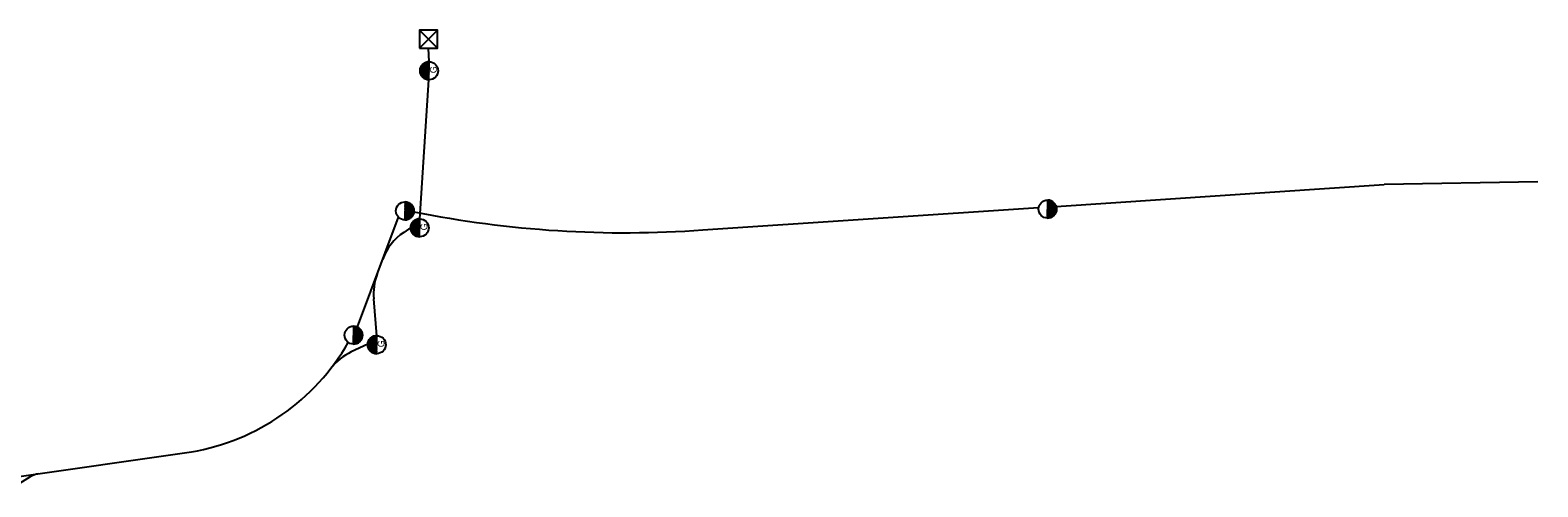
# Model space of a CAD drawing. Extents: x 584850 to 602551, y 145475 to 158627.
# Drawn here: x 586122 to 586791, y 156308 to 156511 of the extents above; entities that cross this region are included whole.
import ezdxf

# ---------------------------------------------------------------- set-up
doc = ezdxf.new("R2010")
doc.units = 0
doc.layers.add('Default', color=7, linetype='Continuous')

msp = doc.modelspace()

# ---------------------------------------------------------------- linework, layer by layer
at = {"layer": 'Default'}
for p, q in [((586294.93, 156502.64), (586302.93, 156510.64)), ((586294.93, 156510.64), (586302.93, 156502.64)), ((586299.27, 156496.61), (586298.93, 156502.64)), ((586299.19, 156496.6), (586295.2, 156492.76)), ((586299.26, 156496.34), (586295.21, 156492.44)), ((586299.26, 156496), (586295.23, 156492.12)), ((586298.82, 156496.58), (586295.24, 156493.14)), ((586299.25, 156495.66), (586295.28, 156491.84)), ((586298.41, 156496.52), (586295.3, 156493.52)), ((586299.24, 156495.32), (586295.34, 156491.56)), ((586299.24, 156494.98), (586295.42, 156491.31)), ((586297.95, 156496.41), (586295.46, 156494.01)), ((586295.47, 156494.05), (586299.15, 156490.23)), ((586299.23, 156494.65), (586295.51, 156491.07)), ((586295.57, 156494.29), (586299.15, 156490.57)), ((586299.22, 156494.31), (586295.61, 156490.83)), ((586295.69, 156494.51), (586299.16, 156490.91)), ((586299.22, 156493.97), (586295.74, 156490.62)), ((586297.33, 156496.15), (586295.75, 156494.62)), ((586295.81, 156494.74), (586299.17, 156491.25)), ((586295.95, 156494.93), (586299.17, 156491.59)), ((586296.1, 156495.13), (586299.18, 156491.93)), ((586296.25, 156495.32), (586299.19, 156492.27)), ((586296.43, 156495.48), (586299.19, 156492.61)), ((586296.6, 156495.64), (586299.2, 156492.95)), ((586296.79, 156495.8), (586299.2, 156493.29)), ((586296.99, 156495.93), (586299.21, 156493.63)), ((586297.2, 156496.07), (586299.22, 156493.97)), ((586297.42, 156496.18), (586299.22, 156494.31)), ((586297.65, 156496.28), (586299.23, 156494.65)), ((586297.89, 156496.39), (586299.24, 156494.98)), ((586298.15, 156496.46), (586299.24, 156495.32)), ((586298.42, 156496.52), (586299.25, 156495.66)), ((586298.71, 156496.57), (586299.26, 156496)), ((586299.02, 156496.59), (586299.26, 156496.34)), ((586299.12, 156488.61), (586299.27, 156496.61)), ((586299.22, 156496.61), (586299.27, 156496.56)), ((586295.1, 156426.81), (586299.12, 156488.61)), ((586295.21, 156492.94), (586299.12, 156488.88)), ((586295.21, 156492.6), (586299.04, 156488.61)), ((586295.21, 156492.24), (586298.67, 156488.65)), ((586295.26, 156493.24), (586299.13, 156489.22)), ((586295.28, 156491.82), (586298.26, 156488.73)), ((586295.3, 156493.53), (586299.13, 156489.56)), ((586295.39, 156493.79), (586299.14, 156489.89)), ((586295.41, 156491.35), (586297.79, 156488.88)), ((586295.68, 156490.72), (586297.17, 156489.18)), ((586299.21, 156493.63), (586295.87, 156490.4)), ((586299.2, 156493.29), (586296, 156490.21)), ((586299.2, 156492.95), (586296.16, 156490.02)), ((586299.19, 156492.61), (586296.32, 156489.84)), ((586299.19, 156492.27), (586296.49, 156489.67)), ((586299.18, 156491.93), (586296.68, 156489.52)), ((586299.17, 156491.59), (586296.86, 156489.36)), ((586299.17, 156491.25), (586297.07, 156489.23)), ((586299.16, 156490.91), (586297.29, 156489.11)), ((586299.15, 156490.57), (586297.51, 156488.99)), ((586299.15, 156490.23), (586297.75, 156488.89)), ((586299.14, 156489.89), (586298, 156488.8)), ((586299.13, 156489.56), (586298.28, 156488.73)), ((586299.13, 156489.22), (586298.56, 156488.67)), ((586299.12, 156488.88), (586298.86, 156488.63)), ((586299.12, 156488.61), (586299.12, 156488.61)), ((586299.12, 156488.61), (586299.12, 156488.61)), ((586303.1, 156493.59), (586303, 156493.55)), ((586577.42, 156432.35), (586723.02, 156442.06)), ((586791.19, 156443.23), (586723.02, 156442.06)), ((586288.53, 156434.33), (586288.38, 156426.33)), ((586288.48, 156431.68), (586290.58, 156433.7)), ((586288.49, 156432.36), (586290.14, 156433.95)), ((586288.49, 156432.02), (586290.36, 156433.83)), ((586288.5, 156432.7), (586289.89, 156434.04)), ((586288.51, 156433.38), (586289.37, 156434.21)), ((586288.51, 156433.04), (586289.65, 156434.14)), ((586288.52, 156433.72), (586289.08, 156434.26)), ((586292.39, 156429.7), (586288.52, 156433.72)), ((586288.53, 156434.33), (586288.53, 156434.32)), ((586288.53, 156434.33), (586288.53, 156434.32)), ((586288.53, 156434.06), (586288.79, 156434.31)), ((586292.44, 156430), (586288.53, 156434.06)), ((586292.44, 156430.34), (586288.61, 156434.32)), ((586292.43, 156430.69), (586288.97, 156434.29)), ((586292.36, 156431.11), (586289.38, 156434.21)), ((586292.24, 156431.59), (586289.86, 156434.06)), ((586291.97, 156432.21), (586290.48, 156433.76)), ((586573.68, 156435.14), (586573.53, 156427.14)), ((586573.6, 156430.8), (586576.64, 156433.73)), ((586573.61, 156431.48), (586576.31, 156434.07)), ((586573.61, 156431.14), (586576.48, 156433.91)), ((586573.62, 156431.82), (586576.12, 156434.23)), ((586573.63, 156432.5), (586575.73, 156434.52)), ((586573.63, 156432.16), (586575.94, 156434.39)), ((586573.64, 156433.17), (586575.29, 156434.76)), ((586573.64, 156432.84), (586575.51, 156434.64)), ((586573.65, 156433.51), (586575.04, 156434.86)), ((586573.66, 156434.19), (586574.52, 156435.02)), ((586573.66, 156433.85), (586574.8, 156434.95)), ((586577.5, 156430.21), (586573.66, 156434.19)), ((586577.41, 156429.95), (586573.66, 156433.85)), ((586573.67, 156434.53), (586574.23, 156435.08)), ((586577.54, 156430.51), (586573.67, 156434.53)), ((586573.68, 156435.14), (586573.68, 156435.14)), ((586573.68, 156435.14), (586573.68, 156435.14)), ((586573.68, 156434.87), (586573.94, 156435.12)), ((586577.59, 156430.81), (586573.68, 156434.87)), ((586577.59, 156431.15), (586573.76, 156435.13)), ((586577.58, 156431.51), (586574.13, 156435.1)), ((586577.51, 156431.93), (586574.53, 156435.02)), ((586577.39, 156432.4), (586575.01, 156434.87)), ((586577.12, 156433.03), (586575.63, 156434.57)), ((586267.37, 156378.76), (586285.6, 156427.53)), ((586288.39, 156426.93), (586292.42, 156430.81)), ((586288.39, 156426.59), (586292.44, 156430.5)), ((586288.4, 156427.27), (586292.37, 156431.09)), ((586289.23, 156426.41), (586288.4, 156427.27)), ((586288.41, 156427.95), (586292.23, 156431.63)), ((586288.41, 156427.61), (586292.31, 156431.38)), ((586289.76, 156426.55), (586288.41, 156427.95)), ((586289.5, 156426.48), (586288.41, 156427.61)), ((586288.42, 156428.63), (586292.03, 156432.11)), ((586288.42, 156428.29), (586292.13, 156431.87)), ((586290.23, 156426.75), (586288.42, 156428.63)), ((586290, 156426.65), (586288.42, 156428.29)), ((586288.43, 156428.97), (586291.91, 156432.32)), ((586290.45, 156426.87), (586288.43, 156428.97)), ((586288.44, 156429.65), (586291.64, 156432.73)), ((586288.44, 156429.31), (586291.78, 156432.53)), ((586290.86, 156427.14), (586288.44, 156429.65)), ((586290.66, 156427), (586288.44, 156429.31)), ((586288.45, 156429.99), (586291.49, 156432.91)), ((586291.05, 156427.29), (586288.45, 156429.99)), ((586288.46, 156430.67), (586291.16, 156433.26)), ((586288.46, 156430.33), (586291.33, 156433.1)), ((586291.4, 156427.62), (586288.46, 156430.67)), ((586291.22, 156427.46), (586288.46, 156430.33)), ((586288.46, 156426.33), (586292.45, 156430.17)), ((586288.47, 156431.01), (586290.97, 156433.42)), ((586291.55, 156427.81), (586288.47, 156431.01)), ((586288.48, 156431.34), (586290.79, 156433.57)), ((586291.84, 156428.2), (586288.48, 156431.68)), ((586291.7, 156428), (586288.48, 156431.34)), ((586292.08, 156428.65), (586288.49, 156432.36)), ((586291.96, 156428.42), (586288.49, 156432.02)), ((586292.18, 156428.88), (586288.5, 156432.7)), ((586292.35, 156429.4), (586288.51, 156433.38)), ((586292.26, 156429.14), (586288.51, 156433.04)), ((586288.83, 156426.36), (586292.41, 156429.8)), ((586289.24, 156426.42), (586292.35, 156429.41)), ((586289.7, 156426.53), (586292.19, 156428.93)), ((586290.32, 156426.79), (586291.9, 156428.31)), ((586420.68, 156421.9), (586569.67, 156431.84)), ((586573.58, 156427.14), (586573.53, 156427.18)), ((586573.54, 156427.75), (586577.57, 156431.63)), ((586573.54, 156427.41), (586577.59, 156431.31)), ((586574.09, 156427.18), (586573.54, 156427.75)), ((586573.78, 156427.16), (586573.54, 156427.41)), ((586573.55, 156428.08), (586577.52, 156431.91)), ((586574.38, 156427.23), (586573.55, 156428.08)), ((586573.56, 156428.76), (586577.38, 156432.44)), ((586573.56, 156428.42), (586577.46, 156432.19)), ((586574.91, 156427.36), (586573.56, 156428.76)), ((586574.65, 156427.29), (586573.56, 156428.42)), ((586573.57, 156429.44), (586577.18, 156432.92)), ((586573.57, 156429.1), (586577.28, 156432.68)), ((586575.38, 156427.56), (586573.57, 156429.44)), ((586575.15, 156427.46), (586573.57, 156429.1)), ((586573.58, 156429.78), (586577.06, 156433.13)), ((586575.6, 156427.68), (586573.58, 156429.78)), ((586573.59, 156430.46), (586576.79, 156433.54)), ((586573.59, 156430.12), (586576.93, 156433.34)), ((586576.01, 156427.95), (586573.59, 156430.46)), ((586575.81, 156427.82), (586573.59, 156430.12)), ((586576.2, 156428.1), (586573.6, 156430.8)), ((586576.55, 156428.43), (586573.61, 156431.48)), ((586576.37, 156428.27), (586573.61, 156431.14)), ((586573.61, 156427.15), (586577.6, 156430.98)), ((586576.7, 156428.62), (586573.62, 156431.82)), ((586576.99, 156429.01), (586573.63, 156432.5)), ((586576.85, 156428.81), (586573.63, 156432.16)), ((586577.23, 156429.46), (586573.64, 156433.17)), ((586577.11, 156429.23), (586573.64, 156432.84)), ((586577.33, 156429.7), (586573.65, 156433.51)), ((586573.98, 156427.17), (586577.56, 156430.61)), ((586574.39, 156427.23), (586577.5, 156430.22)), ((586574.85, 156427.34), (586577.34, 156429.74)), ((586575.47, 156427.6), (586577.05, 156429.12)), ((586291.03, 156422.89), (586287.94, 156420.78)), ((586288.43, 156426.33), (586288.38, 156426.37)), ((586288.94, 156426.36), (586288.39, 156426.93)), ((586288.63, 156426.34), (586288.39, 156426.59)), ((586295.02, 156426.81), (586291.03, 156422.97)), ((586295.1, 156426.55), (586291.04, 156422.64)), ((586291.04, 156423.14), (586294.96, 156419.08)), ((586291.04, 156422.8), (586294.87, 156418.82)), ((586291.05, 156422.45), (586294.51, 156418.86)), ((586295.09, 156426.21), (586291.06, 156422.33)), ((586294.65, 156426.78), (586291.07, 156423.34)), ((586291.09, 156423.44), (586294.96, 156419.42)), ((586295.08, 156425.87), (586291.11, 156422.05)), ((586291.12, 156422.03), (586294.1, 156418.93)), ((586294.24, 156426.72), (586291.13, 156423.73)), ((586291.13, 156423.74), (586294.97, 156419.76)), ((586295.08, 156425.53), (586291.17, 156421.77)), ((586291.22, 156424), (586294.97, 156420.1)), ((586291.24, 156421.55), (586293.62, 156419.08)), ((586295.07, 156425.19), (586291.26, 156421.52)), ((586293.78, 156426.61), (586291.29, 156424.21)), ((586291.3, 156424.26), (586294.98, 156420.44)), ((586295.06, 156424.85), (586291.35, 156421.27)), ((586291.41, 156424.5), (586294.99, 156420.78)), ((586295.06, 156424.51), (586291.45, 156421.03)), ((586291.51, 156420.93), (586293, 156419.38)), ((586291.52, 156424.72), (586294.99, 156421.12)), ((586295.05, 156424.17), (586291.57, 156420.82)), ((586293.16, 156426.35), (586291.58, 156424.83)), ((586291.64, 156424.94), (586295, 156421.46)), ((586295.04, 156423.83), (586291.7, 156420.61)), ((586291.79, 156425.14), (586295.01, 156421.8)), ((586295.04, 156423.49), (586291.84, 156420.41)), ((586291.93, 156425.33), (586295.01, 156422.14)), ((586295.03, 156423.15), (586291.99, 156420.23)), ((586292.08, 156425.52), (586295.02, 156422.47)), ((586295.03, 156422.81), (586292.15, 156420.04)), ((586292.26, 156425.69), (586295.03, 156422.81)), ((586295.02, 156422.47), (586292.32, 156419.88)), ((586292.44, 156425.85), (586295.03, 156423.15)), ((586295.01, 156422.14), (586292.51, 156419.72)), ((586292.62, 156426), (586295.04, 156423.49)), ((586295.01, 156421.8), (586292.69, 156419.57)), ((586292.82, 156426.14), (586295.04, 156423.83)), ((586295, 156421.46), (586292.9, 156419.44)), ((586293.03, 156426.27), (586295.05, 156424.17)), ((586294.99, 156421.12), (586293.12, 156419.31)), ((586293.25, 156426.39), (586295.06, 156424.51)), ((586294.99, 156420.78), (586293.34, 156419.19)), ((586293.48, 156426.49), (586295.06, 156424.85)), ((586294.98, 156420.44), (586293.59, 156419.1)), ((586293.72, 156426.59), (586295.07, 156425.19)), ((586293.98, 156426.66), (586295.08, 156425.53)), ((586294.25, 156426.73), (586295.08, 156425.87)), ((586294.54, 156426.78), (586295.09, 156426.21)), ((586294.85, 156426.8), (586295.1, 156426.55)), ((586294.95, 156418.81), (586295.1, 156426.81)), ((586295.06, 156426.81), (586295.1, 156426.77)), ((586298.93, 156423.8), (586298.83, 156423.75)), ((586294.97, 156420.1), (586293.84, 156419)), ((586294.97, 156419.76), (586294.11, 156418.93)), ((586294.96, 156419.42), (586294.4, 156418.88)), ((586294.96, 156419.08), (586294.69, 156418.83)), ((586294.95, 156418.81), (586294.95, 156418.82)), ((586294.95, 156418.81), (586294.95, 156418.82)), ((586276.08, 156374.9), (586274.65, 156391.28)), ((586265.73, 156379.15), (586265.58, 156371.15)), ((586265.59, 156371.75), (586269.62, 156375.64)), ((586265.59, 156371.41), (586269.64, 156375.32)), ((586265.6, 156372.09), (586269.57, 156375.92)), ((586265.61, 156372.77), (586269.43, 156376.45)), ((586265.61, 156372.43), (586269.51, 156376.2)), ((586265.62, 156373.11), (586269.34, 156376.69)), ((586265.63, 156373.79), (586269.11, 156377.14)), ((586265.63, 156373.45), (586269.24, 156376.93)), ((586267.65, 156371.69), (586265.63, 156373.79)), ((586267.43, 156371.57), (586265.63, 156373.45)), ((586265.64, 156374.47), (586268.84, 156377.55)), ((586265.64, 156374.13), (586268.98, 156377.35)), ((586268.06, 156371.96), (586265.64, 156374.47)), ((586267.86, 156371.82), (586265.64, 156374.13)), ((586265.65, 156374.81), (586268.69, 156377.73)), ((586268.25, 156372.11), (586265.65, 156374.81)), ((586265.66, 156375.49), (586268.36, 156378.08)), ((586265.66, 156375.15), (586268.53, 156377.92)), ((586268.6, 156372.44), (586265.66, 156375.49)), ((586268.42, 156372.28), (586265.66, 156375.15)), ((586265.66, 156371.15), (586269.65, 156374.99)), ((586265.67, 156375.83), (586268.17, 156378.24)), ((586268.75, 156372.63), (586265.67, 156375.83)), ((586265.68, 156376.51), (586267.78, 156378.52)), ((586265.68, 156376.17), (586267.99, 156378.39)), ((586269.04, 156373.02), (586265.68, 156376.51)), ((586268.9, 156372.82), (586265.68, 156376.17)), ((586265.69, 156376.84), (586267.56, 156378.65)), ((586269.16, 156373.24), (586265.69, 156376.84)), ((586265.7, 156377.52), (586267.1, 156378.86)), ((586265.7, 156377.18), (586267.34, 156378.77)), ((586269.38, 156373.71), (586265.7, 156377.52)), ((586269.28, 156373.47), (586265.7, 156377.18)), ((586265.71, 156378.2), (586266.57, 156379.03)), ((586265.71, 156377.86), (586266.85, 156378.96)), ((586269.55, 156374.22), (586265.71, 156378.2)), ((586269.46, 156373.96), (586265.71, 156377.86)), ((586265.72, 156378.54), (586266.29, 156379.09)), ((586269.59, 156374.52), (586265.72, 156378.54)), ((586265.73, 156379.15), (586265.73, 156379.15)), ((586265.73, 156379.15), (586265.73, 156379.15)), ((586265.73, 156378.88), (586265.99, 156379.13)), ((586269.64, 156374.82), (586265.73, 156378.88)), ((586269.64, 156375.16), (586265.81, 156379.14)), ((586266.03, 156371.18), (586269.61, 156374.62)), ((586269.64, 156375.52), (586266.18, 156379.11)), ((586266.44, 156371.24), (586269.55, 156374.23)), ((586269.57, 156375.93), (586266.59, 156379.03)), ((586266.9, 156371.35), (586269.39, 156373.75)), ((586269.44, 156376.41), (586267.06, 156378.88)), ((586269.17, 156377.03), (586267.68, 156378.58)), ((586276, 156374.89), (586272.01, 156371.05)), ((586276.07, 156374.63), (586272.02, 156370.72)), ((586276.06, 156374.29), (586272.04, 156370.41)), ((586275.63, 156374.86), (586272.05, 156371.42)), ((586276.06, 156373.95), (586272.09, 156370.13)), ((586275.22, 156374.81), (586272.11, 156371.81)), ((586276.05, 156373.61), (586272.14, 156369.85)), ((586274.76, 156374.7), (586272.27, 156372.3)), ((586274.14, 156374.43), (586272.56, 156372.91)), ((586273.06, 156373.6), (586275.99, 156370.56)), ((586273.24, 156373.77), (586276, 156370.9)), ((586273.41, 156373.93), (586276.01, 156371.24)), ((586273.6, 156374.09), (586276.01, 156371.57)), ((586273.8, 156374.22), (586276.02, 156371.91)), ((586274.01, 156374.35), (586276.03, 156372.25)), ((586274.22, 156374.47), (586276.03, 156372.59)), ((586274.46, 156374.57), (586276.04, 156372.93)), ((586274.7, 156374.67), (586276.05, 156373.27)), ((586274.96, 156374.74), (586276.05, 156373.61)), ((586275.23, 156374.81), (586276.06, 156373.95)), ((586275.52, 156374.86), (586276.06, 156374.29)), ((586275.83, 156374.88), (586276.07, 156374.63)), ((586275.93, 156366.9), (586276.08, 156374.9)), ((586276.03, 156374.89), (586276.08, 156374.85)), ((586272.01, 156371.17), (586264.67, 156367.68)), ((586265.63, 156371.15), (586265.58, 156371.19)), ((586266.14, 156371.19), (586265.59, 156371.75)), ((586265.83, 156371.16), (586265.59, 156371.41)), ((586266.43, 156371.23), (586265.6, 156372.09)), ((586266.96, 156371.37), (586265.61, 156372.77)), ((586266.7, 156371.3), (586265.61, 156372.43)), ((586267.2, 156371.47), (586265.62, 156373.11)), ((586267.52, 156371.61), (586269.1, 156373.13)), ((586272.01, 156370.88), (586275.85, 156366.9)), ((586272.02, 156371.22), (586275.93, 156367.16)), ((586272.02, 156370.53), (586275.48, 156366.94)), ((586272.06, 156371.52), (586275.94, 156367.5)), ((586272.09, 156370.11), (586275.07, 156367.02)), ((586272.11, 156371.82), (586275.94, 156367.84)), ((586272.2, 156372.08), (586275.95, 156368.18)), ((586272.22, 156369.64), (586274.6, 156367.17)), ((586276.05, 156373.27), (586272.23, 156369.6)), ((586272.28, 156372.34), (586275.96, 156368.52)), ((586276.04, 156372.93), (586272.32, 156369.35)), ((586272.38, 156372.58), (586275.96, 156368.86)), ((586276.03, 156372.59), (586272.42, 156369.12)), ((586272.49, 156369.01), (586273.98, 156367.46)), ((586272.5, 156372.8), (586275.97, 156369.2)), ((586276.03, 156372.25), (586272.55, 156368.9)), ((586272.62, 156373.02), (586275.98, 156369.54)), ((586276.02, 156371.91), (586272.67, 156368.69)), ((586272.76, 156373.22), (586275.98, 156369.88)), ((586276.01, 156371.57), (586272.81, 156368.49)), ((586272.91, 156373.41), (586275.99, 156370.22)), ((586276.01, 156371.24), (586272.97, 156368.31)), ((586276, 156370.9), (586273.12, 156368.13)), ((586275.99, 156370.56), (586273.3, 156367.96)), ((586275.99, 156370.22), (586273.48, 156367.8)), ((586275.98, 156369.88), (586273.67, 156367.65)), ((586275.98, 156369.54), (586273.88, 156367.52)), ((586275.97, 156369.2), (586274.09, 156367.39)), ((586275.96, 156368.86), (586274.31, 156367.27)), ((586275.96, 156368.52), (586274.56, 156367.18)), ((586275.95, 156368.18), (586274.81, 156367.08)), ((586275.94, 156367.84), (586275.08, 156367.01)), ((586275.94, 156367.5), (586275.37, 156366.96)), ((586275.93, 156367.16), (586275.67, 156366.91)), ((586275.93, 156366.9), (586275.93, 156366.9)), ((586275.93, 156366.9), (586275.93, 156366.9)), ((586279.91, 156371.88), (586279.81, 156371.84)), ((586122.18, 156312.13), (586115.12, 156307.73))]:
    msp.add_line(p, q, dxfattribs=at)
msp.add_lwpolyline([(586294.93, 156502.64), (586302.93, 156502.64), (586302.93, 156510.64), (586294.93, 156510.64)], close=True, dxfattribs=at)
msp.add_lwpolyline([(586114.15, 156311.83), (586193.73, 156323.3)], dxfattribs=at)
for centre in [(586299.19, 156492.61), (586288.46, 156430.33), (586573.61, 156431.14), (586295.03, 156422.81), (586265.66, 156375.15), (586276, 156370.9)]:
    msp.add_circle(centre, 4, dxfattribs=at)
for centre, radius, start, end in [((586299.19, 156492.61), 4, 88.92575, 268.92575), ((586288.46, 156430.33), 4, 268.92575, 88.92575), ((586573.61, 156431.14), 4, 268.92575, 88.92575), ((586386.09, 156893.63), 473, 258.58061, 274.1932), ((586302.05, 156400.14), 25, 124.36066, 159.51008), ((586295.03, 156422.81), 4, 88.92575, 268.92575), ((586299.55, 156393.45), 25, 159.51008, 184.98907), ((586265.66, 156375.15), 4, 268.92575, 88.92575), ((586276, 156370.9), 4, 88.92575, 268.92575), ((586176.72, 156421.84), 100, 279.79341, 330.02637), ((586275.39, 156345.1), 25, 115.39002, 142.12314), ((586127.47, 156303.64), 10, 98.20522, 121.91658)]:
    msp.add_arc(centre, radius, start, end, dxfattribs=at)

# ---------------------------------------------------------------- texts
for p in [(586302.57, 156491.48), (586298.4, 156421.68), (586279.38, 156369.76)]:
    msp.add_text('G', height=3, rotation=89.36227, dxfattribs=at).set_placement(p)

doc.saveas('drawing.dxf')
